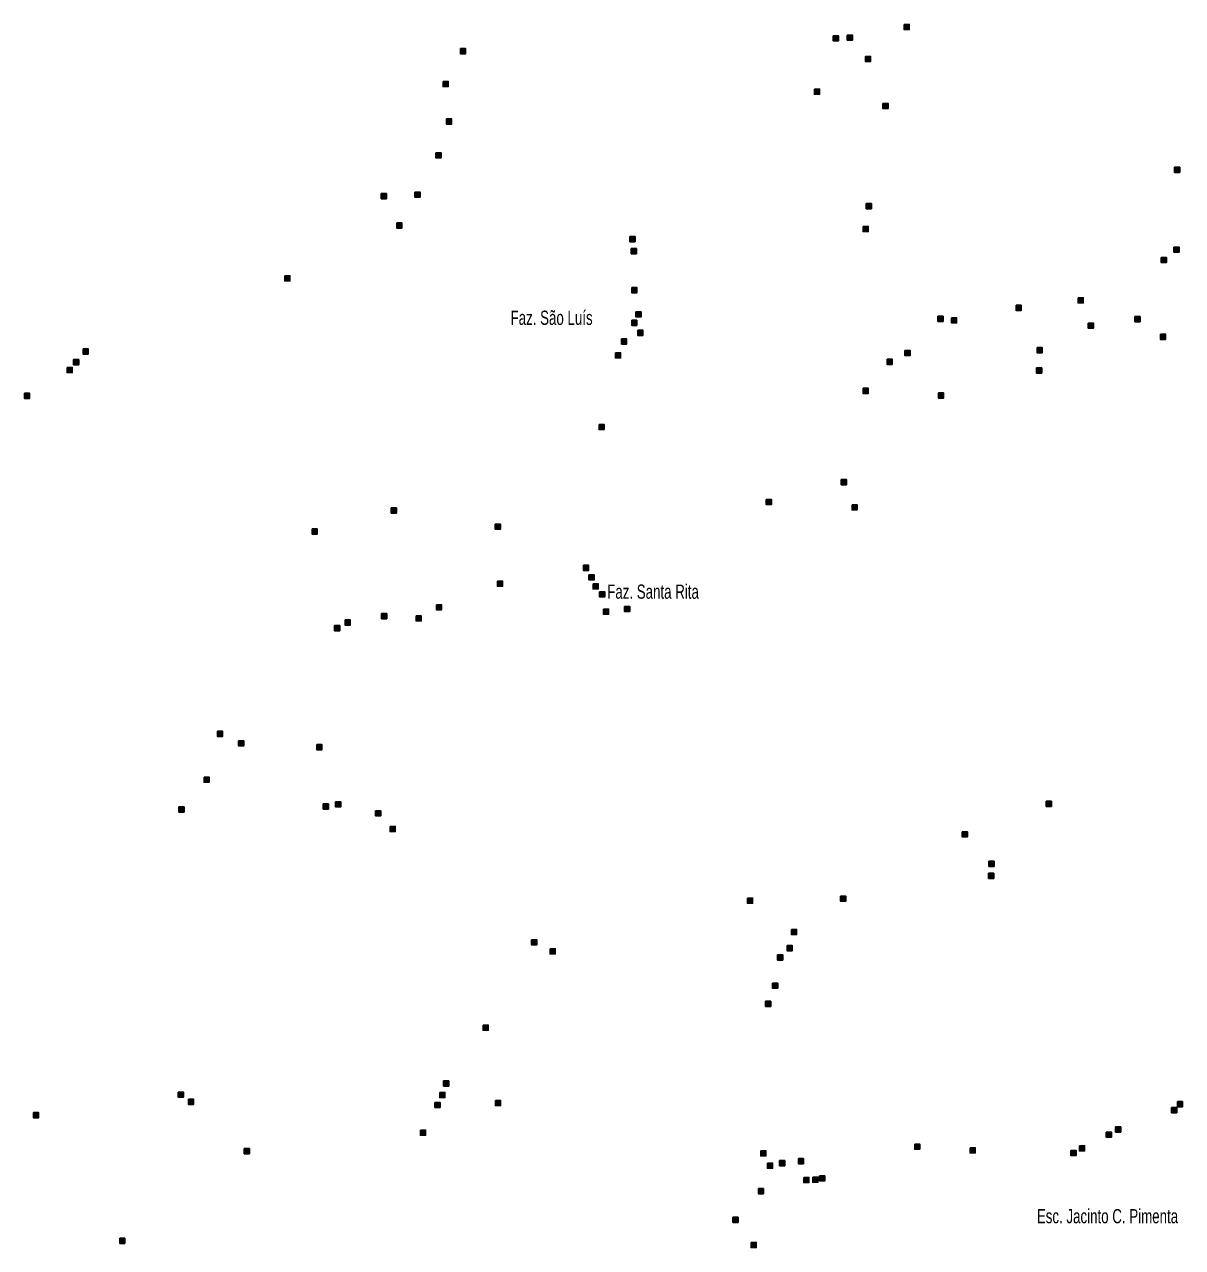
# Model space of a CAD drawing. Extents: x 265.7 to 292.1, y 7676.2 to 7704.2.
# Drawn here: x 272.51 to 279.03, y 7690.25 to 7697.13 of the extents above; entities that cross this region are included whole.
import ezdxf

# ---------------------------------------------------------------- set-up
doc = ezdxf.new("R2010")
doc.units = 0
doc.header["$LTSCALE"] = 0.032
doc.layers.add('2', color=7, linetype='Continuous', lineweight=25)
doc.layers.add('61', color=7, linetype='Continuous')

msp = doc.modelspace()

# ---------------------------------------------------------------- hatches: boundary and pattern name
at = {"layer": '2'}
for points in [[(277.4581, 7697.1299), (277.4871, 7697.1299), (277.4871, 7697.1009), (277.4581, 7697.1009)], [(277.0601, 7697.066), (277.0891, 7697.066), (277.0891, 7697.037), (277.0601, 7697.037)], [(277.1385, 7697.0701), (277.1675, 7697.0701), (277.1675, 7697.0411), (277.1385, 7697.0411)], [(274.9619, 7696.9942), (274.9909, 7696.9942), (274.9909, 7696.9652), (274.9619, 7696.9652)], [(277.241, 7696.9506), (277.27, 7696.9506), (277.27, 7696.9216), (277.241, 7696.9216)], [(274.8643, 7696.8093), (274.8933, 7696.8093), (274.8933, 7696.7803), (274.8643, 7696.7803)], [(276.9537, 7696.7666), (276.9827, 7696.7666), (276.9827, 7696.7376), (276.9537, 7696.7376)], [(277.3394, 7696.6859), (277.3684, 7696.6859), (277.3684, 7696.6569), (277.3394, 7696.6569)], [(274.8829, 7696.5988), (274.9119, 7696.5988), (274.9119, 7696.5698), (274.8829, 7696.5698)], [(274.8239, 7696.4084), (274.8529, 7696.4084), (274.8529, 7696.3794), (274.8239, 7696.3794)], [(278.9802, 7696.3268), (279.0092, 7696.3268), (279.0092, 7696.2978), (278.9802, 7696.2978)], [(274.5164, 7696.1783), (274.5454, 7696.1783), (274.5454, 7696.1493), (274.5164, 7696.1493)], [(274.7061, 7696.1872), (274.7351, 7696.1872), (274.7351, 7696.1582), (274.7061, 7696.1582)], [(277.2451, 7696.1219), (277.2741, 7696.1219), (277.2741, 7696.0929), (277.2451, 7696.0929)], [(274.6036, 7696.0138), (274.6326, 7696.0138), (274.6326, 7695.9848), (274.6036, 7695.9848)], [(277.2274, 7695.9934), (277.2564, 7695.9934), (277.2564, 7695.9644), (277.2274, 7695.9644)], [(275.9158, 7695.9362), (275.9448, 7695.9362), (275.9448, 7695.9072), (275.9158, 7695.9072)], [(275.9231, 7695.8693), (275.9521, 7695.8693), (275.9521, 7695.8403), (275.9231, 7695.8403)], [(278.9771, 7695.8773), (279.0061, 7695.8773), (279.0061, 7695.8483), (278.9771, 7695.8483)], [(278.9053, 7695.8192), (278.9343, 7695.8192), (278.9343, 7695.7902), (278.9053, 7695.7902)], [(273.973, 7695.7167), (274.002, 7695.7167), (274.002, 7695.6877), (273.973, 7695.6877)], [(275.9256, 7695.6497), (275.9546, 7695.6497), (275.9546, 7695.6207), (275.9256, 7695.6207)], [(278.4378, 7695.5924), (278.4668, 7695.5924), (278.4668, 7695.5634), (278.4378, 7695.5634)], [(275.9497, 7695.5142), (275.9787, 7695.5142), (275.9787, 7695.4852), (275.9497, 7695.4852)], [(278.0883, 7695.5504), (278.1173, 7695.5504), (278.1173, 7695.5214), (278.0883, 7695.5214)], [(275.9254, 7695.4656), (275.9544, 7695.4656), (275.9544, 7695.4366), (275.9254, 7695.4366)], [(277.6485, 7695.4882), (277.6775, 7695.4882), (277.6775, 7695.4592), (277.6485, 7695.4592)], [(277.7252, 7695.4802), (277.7542, 7695.4802), (277.7542, 7695.4512), (277.7252, 7695.4512)], [(278.4944, 7695.4496), (278.5234, 7695.4496), (278.5234, 7695.4206), (278.4944, 7695.4206)], [(278.7575, 7695.4866), (278.7865, 7695.4866), (278.7865, 7695.4576), (278.7575, 7695.4576)], [(275.9594, 7695.41), (275.9884, 7695.41), (275.9884, 7695.381), (275.9594, 7695.381)], [(278.9011, 7695.3875), (278.9301, 7695.3875), (278.9301, 7695.3585), (278.9011, 7695.3585)], [(272.8385, 7695.305), (272.8675, 7695.305), (272.8675, 7695.276), (272.8385, 7695.276)], [(275.8682, 7695.3607), (275.8972, 7695.3607), (275.8972, 7695.3317), (275.8682, 7695.3317)], [(278.2071, 7695.3123), (278.2361, 7695.3123), (278.2361, 7695.2833), (278.2071, 7695.2833)], [(272.7853, 7695.2446), (272.8143, 7695.2446), (272.8143, 7695.2156), (272.7853, 7695.2156)], [(275.8344, 7695.2832), (275.8634, 7695.2832), (275.8634, 7695.2542), (275.8344, 7695.2542)], [(277.363, 7695.2462), (277.392, 7695.2462), (277.392, 7695.2172), (277.363, 7695.2172)], [(277.4629, 7695.2962), (277.4919, 7695.2962), (277.4919, 7695.2672), (277.4629, 7695.2672)], [(272.7481, 7695.201), (272.7771, 7695.201), (272.7771, 7695.172), (272.7481, 7695.172)], [(278.2038, 7695.1978), (278.2328, 7695.1978), (278.2328, 7695.1688), (278.2038, 7695.1688)], [(272.5085, 7695.0556), (272.5375, 7695.0556), (272.5375, 7695.0266), (272.5085, 7695.0266)], [(277.2273, 7695.0831), (277.2563, 7695.0831), (277.2563, 7695.0541), (277.2273, 7695.0541)], [(277.6519, 7695.0573), (277.6809, 7695.0573), (277.6809, 7695.0283), (277.6519, 7695.0283)], [(275.7416, 7694.8797), (275.7706, 7694.8797), (275.7706, 7694.8507), (275.7416, 7694.8507)], [(277.1046, 7694.5698), (277.1336, 7694.5698), (277.1336, 7694.5408), (277.1046, 7694.5408)], [(274.5722, 7694.41), (274.6012, 7694.41), (274.6012, 7694.381), (274.5722, 7694.381)], [(276.6826, 7694.4584), (276.7116, 7694.4584), (276.7116, 7694.4294), (276.6826, 7694.4294)], [(277.1653, 7694.4278), (277.1943, 7694.4278), (277.1943, 7694.3988), (277.1653, 7694.3988)], [(274.1275, 7694.2922), (274.1565, 7694.2922), (274.1565, 7694.2632), (274.1275, 7694.2632)], [(275.158, 7694.3189), (275.187, 7694.3189), (275.187, 7694.2899), (275.158, 7694.2899)], [(275.6539, 7694.0877), (275.6829, 7694.0877), (275.6829, 7694.0587), (275.6539, 7694.0587)], [(275.1702, 7693.9985), (275.1992, 7693.9985), (275.1992, 7693.9695), (275.1702, 7693.9695)], [(275.685, 7694.0339), (275.714, 7694.0339), (275.714, 7694.0049), (275.685, 7694.0049)], [(275.7085, 7693.9832), (275.7375, 7693.9832), (275.7375, 7693.9542), (275.7085, 7693.9542)], [(275.7448, 7693.9387), (275.7738, 7693.9387), (275.7738, 7693.9097), (275.7448, 7693.9097)], [(274.8271, 7693.866), (274.8561, 7693.866), (274.8561, 7693.837), (274.8271, 7693.837)], [(275.886, 7693.8564), (275.915, 7693.8564), (275.915, 7693.8274), (275.886, 7693.8274)], [(274.5181, 7693.8161), (274.5471, 7693.8161), (274.5471, 7693.7871), (274.5181, 7693.7871)], [(274.7126, 7693.8032), (274.7416, 7693.8032), (274.7416, 7693.7742), (274.7126, 7693.7742)], [(275.7666, 7693.8411), (275.7956, 7693.8411), (275.7956, 7693.8121), (275.7666, 7693.8121)], [(274.2533, 7693.7482), (274.2823, 7693.7482), (274.2823, 7693.7192), (274.2533, 7693.7192)], [(274.313, 7693.7805), (274.342, 7693.7805), (274.342, 7693.7515), (274.313, 7693.7515)], [(273.594, 7693.1543), (273.623, 7693.1543), (273.623, 7693.1253), (273.594, 7693.1253)], [(273.7134, 7693.1002), (273.7424, 7693.1002), (273.7424, 7693.0712), (273.7134, 7693.0712)], [(274.1533, 7693.0792), (274.1823, 7693.0792), (274.1823, 7693.0502), (274.1533, 7693.0502)], [(273.5189, 7692.896), (273.5479, 7692.896), (273.5479, 7692.867), (273.5189, 7692.867)], [(274.259, 7692.7573), (274.288, 7692.7573), (274.288, 7692.7283), (274.259, 7692.7283)], [(278.2586, 7692.7604), (278.2876, 7692.7604), (278.2876, 7692.7314), (278.2586, 7692.7314)], [(273.3777, 7692.7282), (273.4067, 7692.7282), (273.4067, 7692.6992), (273.3777, 7692.6992)], [(274.1896, 7692.7451), (274.2186, 7692.7451), (274.2186, 7692.7161), (274.1896, 7692.7161)], [(274.4841, 7692.7072), (274.5131, 7692.7072), (274.5131, 7692.6782), (274.4841, 7692.6782)], [(274.5657, 7692.6185), (274.5947, 7692.6185), (274.5947, 7692.5895), (274.5657, 7692.5895)], [(277.7858, 7692.5885), (277.8148, 7692.5885), (277.8148, 7692.5595), (277.7858, 7692.5595)], [(277.936, 7692.4223), (277.965, 7692.4223), (277.965, 7692.3933), (277.936, 7692.3933)], [(277.9343, 7692.3553), (277.9633, 7692.3553), (277.9633, 7692.3263), (277.9343, 7692.3263)], [(276.5768, 7692.2157), (276.6058, 7692.2157), (276.6058, 7692.1867), (276.5768, 7692.1867)], [(277.1007, 7692.227), (277.1297, 7692.227), (277.1297, 7692.198), (277.1007, 7692.198)], [(276.8246, 7692.0389), (276.8536, 7692.0389), (276.8536, 7692.0099), (276.8246, 7692.0099)], [(275.3622, 7691.9808), (275.3912, 7691.9808), (275.3912, 7691.9518), (275.3622, 7691.9518)], [(275.4663, 7691.9307), (275.4953, 7691.9307), (275.4953, 7691.9017), (275.4663, 7691.9017)], [(276.7996, 7691.9486), (276.8286, 7691.9486), (276.8286, 7691.9196), (276.7996, 7691.9196)], [(276.7462, 7691.8961), (276.7752, 7691.8961), (276.7752, 7691.8671), (276.7462, 7691.8671)], [(276.718, 7691.7372), (276.747, 7691.7372), (276.747, 7691.7082), (276.718, 7691.7082)], [(276.6793, 7691.6354), (276.7083, 7691.6354), (276.7083, 7691.6064), (276.6793, 7691.6064)], [(275.0894, 7691.5014), (275.1184, 7691.5014), (275.1184, 7691.4724), (275.0894, 7691.4724)], [(274.8667, 7691.1867), (274.8957, 7691.1867), (274.8957, 7691.1577), (274.8667, 7691.1577)], [(273.3737, 7691.1245), (273.4027, 7691.1245), (273.4027, 7691.0955), (273.3737, 7691.0955)], [(274.8457, 7691.1221), (274.8747, 7691.1221), (274.8747, 7691.0931), (274.8457, 7691.0931)], [(273.431, 7691.0842), (273.46, 7691.0842), (273.46, 7691.0552), (273.431, 7691.0552)], [(274.8184, 7691.0665), (274.8474, 7691.0665), (274.8474, 7691.0375), (274.8184, 7691.0375)], [(275.1587, 7691.0769), (275.1877, 7691.0769), (275.1877, 7691.0479), (275.1587, 7691.0479)], [(278.964, 7691.0366), (278.993, 7691.0366), (278.993, 7691.0076), (278.964, 7691.0076)], [(278.9963, 7691.0705), (279.0253, 7691.0705), (279.0253, 7691.0415), (278.9963, 7691.0415)], [(272.5593, 7691.0084), (272.5883, 7691.0084), (272.5883, 7690.9794), (272.5593, 7690.9794)], [(274.7367, 7690.9106), (274.7657, 7690.9106), (274.7657, 7690.8816), (274.7367, 7690.8816)], [(278.5961, 7690.8994), (278.6251, 7690.8994), (278.6251, 7690.8704), (278.5961, 7690.8704)], [(278.6485, 7690.9284), (278.6775, 7690.9284), (278.6775, 7690.8994), (278.6485, 7690.8994)], [(277.5179, 7690.8317), (277.5469, 7690.8317), (277.5469, 7690.8027), (277.5179, 7690.8027)], [(273.7458, 7690.8066), (273.7748, 7690.8066), (273.7748, 7690.7776), (273.7458, 7690.7776)], [(276.6519, 7690.7945), (276.6809, 7690.7945), (276.6809, 7690.7655), (276.6519, 7690.7655)], [(277.8294, 7690.8106), (277.8584, 7690.8106), (277.8584, 7690.7816), (277.8294, 7690.7816)], [(278.3976, 7690.7961), (278.4266, 7690.7961), (278.4266, 7690.7671), (278.3976, 7690.7671)], [(278.4451, 7690.8219), (278.4741, 7690.8219), (278.4741, 7690.7929), (278.4451, 7690.7929)], [(276.6897, 7690.7251), (276.7187, 7690.7251), (276.7187, 7690.6961), (276.6897, 7690.6961)], [(276.7574, 7690.7387), (276.7864, 7690.7387), (276.7864, 7690.7097), (276.7574, 7690.7097)], [(276.8633, 7690.7497), (276.8923, 7690.7497), (276.8923, 7690.7207), (276.8633, 7690.7207)], [(276.8939, 7690.6444), (276.9229, 7690.6444), (276.9229, 7690.6154), (276.8939, 7690.6154)], [(276.944, 7690.646), (276.973, 7690.646), (276.973, 7690.617), (276.944, 7690.617)], [(276.9827, 7690.6533), (277.0117, 7690.6533), (277.0117, 7690.6243), (276.9827, 7690.6243)], [(276.6382, 7690.5813), (276.6672, 7690.5813), (276.6672, 7690.5523), (276.6382, 7690.5523)], [(276.4953, 7690.42), (276.5243, 7690.42), (276.5243, 7690.391), (276.4953, 7690.391)], [(273.0443, 7690.3015), (273.0733, 7690.3015), (273.0733, 7690.2725), (273.0443, 7690.2725)], [(276.597, 7690.2787), (276.626, 7690.2787), (276.626, 7690.2497), (276.597, 7690.2497)]]:
    msp.add_hatch(color=256, dxfattribs=at).paths.add_polyline_path(points)

# ---------------------------------------------------------------- linework, layer by layer
for points in [[(277.4581, 7697.1299), (277.4871, 7697.1299), (277.4871, 7697.1009), (277.4581, 7697.1009)], [(277.0601, 7697.066), (277.0891, 7697.066), (277.0891, 7697.037), (277.0601, 7697.037)], [(277.1385, 7697.0701), (277.1675, 7697.0701), (277.1675, 7697.0411), (277.1385, 7697.0411)], [(274.9619, 7696.9942), (274.9909, 7696.9942), (274.9909, 7696.9652), (274.9619, 7696.9652)], [(277.241, 7696.9506), (277.27, 7696.9506), (277.27, 7696.9216), (277.241, 7696.9216)], [(274.8643, 7696.8093), (274.8933, 7696.8093), (274.8933, 7696.7803), (274.8643, 7696.7803)], [(276.9537, 7696.7666), (276.9827, 7696.7666), (276.9827, 7696.7376), (276.9537, 7696.7376)], [(277.3394, 7696.6859), (277.3684, 7696.6859), (277.3684, 7696.6569), (277.3394, 7696.6569)], [(274.8829, 7696.5988), (274.9119, 7696.5988), (274.9119, 7696.5698), (274.8829, 7696.5698)], [(274.8239, 7696.4084), (274.8529, 7696.4084), (274.8529, 7696.3794), (274.8239, 7696.3794)], [(278.9802, 7696.3268), (279.0092, 7696.3268), (279.0092, 7696.2978), (278.9802, 7696.2978)], [(274.5164, 7696.1783), (274.5454, 7696.1783), (274.5454, 7696.1493), (274.5164, 7696.1493)], [(274.7061, 7696.1872), (274.7351, 7696.1872), (274.7351, 7696.1582), (274.7061, 7696.1582)], [(277.2451, 7696.1219), (277.2741, 7696.1219), (277.2741, 7696.0929), (277.2451, 7696.0929)], [(274.6036, 7696.0138), (274.6326, 7696.0138), (274.6326, 7695.9848), (274.6036, 7695.9848)], [(277.2274, 7695.9934), (277.2564, 7695.9934), (277.2564, 7695.9644), (277.2274, 7695.9644)], [(275.9158, 7695.9362), (275.9448, 7695.9362), (275.9448, 7695.9072), (275.9158, 7695.9072)], [(275.9231, 7695.8693), (275.9521, 7695.8693), (275.9521, 7695.8403), (275.9231, 7695.8403)], [(278.9771, 7695.8773), (279.0061, 7695.8773), (279.0061, 7695.8483), (278.9771, 7695.8483)], [(278.9053, 7695.8192), (278.9343, 7695.8192), (278.9343, 7695.7902), (278.9053, 7695.7902)], [(273.973, 7695.7167), (274.002, 7695.7167), (274.002, 7695.6877), (273.973, 7695.6877)], [(275.9256, 7695.6497), (275.9546, 7695.6497), (275.9546, 7695.6207), (275.9256, 7695.6207)], [(278.4378, 7695.5924), (278.4668, 7695.5924), (278.4668, 7695.5634), (278.4378, 7695.5634)], [(275.9497, 7695.5142), (275.9787, 7695.5142), (275.9787, 7695.4852), (275.9497, 7695.4852)], [(278.0883, 7695.5504), (278.1173, 7695.5504), (278.1173, 7695.5214), (278.0883, 7695.5214)], [(275.9254, 7695.4656), (275.9544, 7695.4656), (275.9544, 7695.4366), (275.9254, 7695.4366)], [(277.6485, 7695.4882), (277.6775, 7695.4882), (277.6775, 7695.4592), (277.6485, 7695.4592)], [(277.7252, 7695.4802), (277.7542, 7695.4802), (277.7542, 7695.4512), (277.7252, 7695.4512)], [(278.4944, 7695.4496), (278.5234, 7695.4496), (278.5234, 7695.4206), (278.4944, 7695.4206)], [(278.7575, 7695.4866), (278.7865, 7695.4866), (278.7865, 7695.4576), (278.7575, 7695.4576)], [(275.9594, 7695.41), (275.9884, 7695.41), (275.9884, 7695.381), (275.9594, 7695.381)], [(278.9011, 7695.3875), (278.9301, 7695.3875), (278.9301, 7695.3585), (278.9011, 7695.3585)], [(272.8385, 7695.305), (272.8675, 7695.305), (272.8675, 7695.276), (272.8385, 7695.276)], [(275.8682, 7695.3607), (275.8972, 7695.3607), (275.8972, 7695.3317), (275.8682, 7695.3317)], [(278.2071, 7695.3123), (278.2361, 7695.3123), (278.2361, 7695.2833), (278.2071, 7695.2833)], [(272.7853, 7695.2446), (272.8143, 7695.2446), (272.8143, 7695.2156), (272.7853, 7695.2156)], [(275.8344, 7695.2832), (275.8634, 7695.2832), (275.8634, 7695.2542), (275.8344, 7695.2542)], [(277.363, 7695.2462), (277.392, 7695.2462), (277.392, 7695.2172), (277.363, 7695.2172)], [(277.4629, 7695.2962), (277.4919, 7695.2962), (277.4919, 7695.2672), (277.4629, 7695.2672)], [(272.7481, 7695.201), (272.7771, 7695.201), (272.7771, 7695.172), (272.7481, 7695.172)], [(278.2038, 7695.1978), (278.2328, 7695.1978), (278.2328, 7695.1688), (278.2038, 7695.1688)], [(272.5085, 7695.0556), (272.5375, 7695.0556), (272.5375, 7695.0266), (272.5085, 7695.0266)], [(277.2273, 7695.0831), (277.2563, 7695.0831), (277.2563, 7695.0541), (277.2273, 7695.0541)], [(277.6519, 7695.0573), (277.6809, 7695.0573), (277.6809, 7695.0283), (277.6519, 7695.0283)], [(275.7416, 7694.8797), (275.7706, 7694.8797), (275.7706, 7694.8507), (275.7416, 7694.8507)], [(277.1046, 7694.5698), (277.1336, 7694.5698), (277.1336, 7694.5408), (277.1046, 7694.5408)], [(274.5722, 7694.41), (274.6012, 7694.41), (274.6012, 7694.381), (274.5722, 7694.381)], [(276.6826, 7694.4584), (276.7116, 7694.4584), (276.7116, 7694.4294), (276.6826, 7694.4294)], [(277.1653, 7694.4278), (277.1943, 7694.4278), (277.1943, 7694.3988), (277.1653, 7694.3988)], [(274.1275, 7694.2922), (274.1565, 7694.2922), (274.1565, 7694.2632), (274.1275, 7694.2632)], [(275.158, 7694.3189), (275.187, 7694.3189), (275.187, 7694.2899), (275.158, 7694.2899)], [(275.6539, 7694.0877), (275.6829, 7694.0877), (275.6829, 7694.0587), (275.6539, 7694.0587)], [(275.1702, 7693.9985), (275.1992, 7693.9985), (275.1992, 7693.9695), (275.1702, 7693.9695)], [(275.685, 7694.0339), (275.714, 7694.0339), (275.714, 7694.0049), (275.685, 7694.0049)], [(275.7085, 7693.9832), (275.7375, 7693.9832), (275.7375, 7693.9542), (275.7085, 7693.9542)], [(275.7448, 7693.9387), (275.7738, 7693.9387), (275.7738, 7693.9097), (275.7448, 7693.9097)], [(274.8271, 7693.866), (274.8561, 7693.866), (274.8561, 7693.837), (274.8271, 7693.837)], [(275.886, 7693.8564), (275.915, 7693.8564), (275.915, 7693.8274), (275.886, 7693.8274)], [(274.5181, 7693.8161), (274.5471, 7693.8161), (274.5471, 7693.7871), (274.5181, 7693.7871)], [(274.7126, 7693.8032), (274.7416, 7693.8032), (274.7416, 7693.7742), (274.7126, 7693.7742)], [(275.7666, 7693.8411), (275.7956, 7693.8411), (275.7956, 7693.8121), (275.7666, 7693.8121)], [(274.2533, 7693.7482), (274.2823, 7693.7482), (274.2823, 7693.7192), (274.2533, 7693.7192)], [(274.313, 7693.7805), (274.342, 7693.7805), (274.342, 7693.7515), (274.313, 7693.7515)], [(273.594, 7693.1543), (273.623, 7693.1543), (273.623, 7693.1253), (273.594, 7693.1253)], [(273.7134, 7693.1002), (273.7424, 7693.1002), (273.7424, 7693.0712), (273.7134, 7693.0712)], [(274.1533, 7693.0792), (274.1823, 7693.0792), (274.1823, 7693.0502), (274.1533, 7693.0502)], [(273.5189, 7692.896), (273.5479, 7692.896), (273.5479, 7692.867), (273.5189, 7692.867)], [(274.259, 7692.7573), (274.288, 7692.7573), (274.288, 7692.7283), (274.259, 7692.7283)], [(278.2586, 7692.7604), (278.2876, 7692.7604), (278.2876, 7692.7314), (278.2586, 7692.7314)], [(273.3777, 7692.7282), (273.4067, 7692.7282), (273.4067, 7692.6992), (273.3777, 7692.6992)], [(274.1896, 7692.7451), (274.2186, 7692.7451), (274.2186, 7692.7161), (274.1896, 7692.7161)], [(274.4841, 7692.7072), (274.5131, 7692.7072), (274.5131, 7692.6782), (274.4841, 7692.6782)], [(274.5657, 7692.6185), (274.5947, 7692.6185), (274.5947, 7692.5895), (274.5657, 7692.5895)], [(277.7858, 7692.5885), (277.8148, 7692.5885), (277.8148, 7692.5595), (277.7858, 7692.5595)], [(277.936, 7692.4223), (277.965, 7692.4223), (277.965, 7692.3933), (277.936, 7692.3933)], [(277.9343, 7692.3553), (277.9633, 7692.3553), (277.9633, 7692.3263), (277.9343, 7692.3263)], [(276.5768, 7692.2157), (276.6058, 7692.2157), (276.6058, 7692.1867), (276.5768, 7692.1867)], [(277.1007, 7692.227), (277.1297, 7692.227), (277.1297, 7692.198), (277.1007, 7692.198)], [(276.8246, 7692.0389), (276.8536, 7692.0389), (276.8536, 7692.0099), (276.8246, 7692.0099)], [(275.3622, 7691.9808), (275.3912, 7691.9808), (275.3912, 7691.9518), (275.3622, 7691.9518)], [(275.4663, 7691.9307), (275.4953, 7691.9307), (275.4953, 7691.9017), (275.4663, 7691.9017)], [(276.7996, 7691.9486), (276.8286, 7691.9486), (276.8286, 7691.9196), (276.7996, 7691.9196)], [(276.7462, 7691.8961), (276.7752, 7691.8961), (276.7752, 7691.8671), (276.7462, 7691.8671)], [(276.718, 7691.7372), (276.747, 7691.7372), (276.747, 7691.7082), (276.718, 7691.7082)], [(276.6793, 7691.6354), (276.7083, 7691.6354), (276.7083, 7691.6064), (276.6793, 7691.6064)], [(275.0894, 7691.5014), (275.1184, 7691.5014), (275.1184, 7691.4724), (275.0894, 7691.4724)], [(274.8667, 7691.1867), (274.8957, 7691.1867), (274.8957, 7691.1577), (274.8667, 7691.1577)], [(273.3737, 7691.1245), (273.4027, 7691.1245), (273.4027, 7691.0955), (273.3737, 7691.0955)], [(274.8457, 7691.1221), (274.8747, 7691.1221), (274.8747, 7691.0931), (274.8457, 7691.0931)], [(273.431, 7691.0842), (273.46, 7691.0842), (273.46, 7691.0552), (273.431, 7691.0552)], [(274.8184, 7691.0665), (274.8474, 7691.0665), (274.8474, 7691.0375), (274.8184, 7691.0375)], [(275.1587, 7691.0769), (275.1877, 7691.0769), (275.1877, 7691.0479), (275.1587, 7691.0479)], [(278.964, 7691.0366), (278.993, 7691.0366), (278.993, 7691.0076), (278.964, 7691.0076)], [(278.9963, 7691.0705), (279.0253, 7691.0705), (279.0253, 7691.0415), (278.9963, 7691.0415)], [(272.5593, 7691.0084), (272.5883, 7691.0084), (272.5883, 7690.9794), (272.5593, 7690.9794)], [(274.7367, 7690.9106), (274.7657, 7690.9106), (274.7657, 7690.8816), (274.7367, 7690.8816)], [(278.5961, 7690.8994), (278.6251, 7690.8994), (278.6251, 7690.8704), (278.5961, 7690.8704)], [(278.6485, 7690.9284), (278.6775, 7690.9284), (278.6775, 7690.8994), (278.6485, 7690.8994)], [(277.5179, 7690.8317), (277.5469, 7690.8317), (277.5469, 7690.8027), (277.5179, 7690.8027)], [(273.7458, 7690.8066), (273.7748, 7690.8066), (273.7748, 7690.7776), (273.7458, 7690.7776)], [(276.6519, 7690.7945), (276.6809, 7690.7945), (276.6809, 7690.7655), (276.6519, 7690.7655)], [(277.8294, 7690.8106), (277.8584, 7690.8106), (277.8584, 7690.7816), (277.8294, 7690.7816)], [(278.3976, 7690.7961), (278.4266, 7690.7961), (278.4266, 7690.7671), (278.3976, 7690.7671)], [(278.4451, 7690.8219), (278.4741, 7690.8219), (278.4741, 7690.7929), (278.4451, 7690.7929)], [(276.6897, 7690.7251), (276.7187, 7690.7251), (276.7187, 7690.6961), (276.6897, 7690.6961)], [(276.7574, 7690.7387), (276.7864, 7690.7387), (276.7864, 7690.7097), (276.7574, 7690.7097)], [(276.8633, 7690.7497), (276.8923, 7690.7497), (276.8923, 7690.7207), (276.8633, 7690.7207)], [(276.8939, 7690.6444), (276.9229, 7690.6444), (276.9229, 7690.6154), (276.8939, 7690.6154)], [(276.944, 7690.646), (276.973, 7690.646), (276.973, 7690.617), (276.944, 7690.617)], [(276.9827, 7690.6533), (277.0117, 7690.6533), (277.0117, 7690.6243), (276.9827, 7690.6243)], [(276.6382, 7690.5813), (276.6672, 7690.5813), (276.6672, 7690.5523), (276.6382, 7690.5523)], [(276.4953, 7690.42), (276.5243, 7690.42), (276.5243, 7690.391), (276.4953, 7690.391)], [(273.0443, 7690.3015), (273.0733, 7690.3015), (273.0733, 7690.2725), (273.0443, 7690.2725)], [(276.597, 7690.2787), (276.626, 7690.2787), (276.626, 7690.2497), (276.597, 7690.2497)]]:
    msp.add_lwpolyline(points, close=True, dxfattribs=at)

# ---------------------------------------------------------------- texts
at = {"layer": '61', "width": 0.7}
for s, p in [('Faz. São Luís', (275.2438, 7695.4401)), ('Faz. Santa Rita', (275.7877, 7693.8994)), ('Esc. Jacinto C. Pimenta', (278.2055, 7690.3861))]:
    msp.add_text(s, height=0.08, dxfattribs=at).set_placement(p)

doc.saveas('drawing.dxf')
